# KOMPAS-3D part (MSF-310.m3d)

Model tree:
1. Ось X
2. Ось Y
3. Ось Z
4. Начало координат  (labels: Операция без истории:1)

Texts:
  Линия-выноска #1
  Линия-выноска #2
  Линия-выноска #3
  Отклонения формы и база
  Марка координационной оси
  Марка/позиционное обозначение с линией-выноской
  Марка/позиционное обозначение на линии
  Марка/позиционное обозначение без линии-выноски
